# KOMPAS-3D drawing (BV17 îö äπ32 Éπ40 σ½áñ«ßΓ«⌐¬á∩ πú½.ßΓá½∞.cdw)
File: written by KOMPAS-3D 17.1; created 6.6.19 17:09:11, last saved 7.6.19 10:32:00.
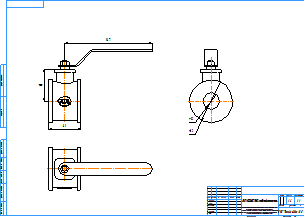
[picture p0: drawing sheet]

Sheet 1: A2, landscape

Title block, sheet 1: name: BV17 МФ Ду32 Ру40 хладостойкая угл.сталь; material: Сталь 20  ГОСТ 1050-2013; mass: 1,6; sheets: 1; sheet format: A2; stored path: C:\Users\kka\KOMPAS_Work\!Trash\BV17 МФ хладостойкая угл.сталь Ру40\KOMPAS 2D\BV17 МФ Ду20 Ру40 хладостойкая угл.сталь.cdw

Views: Вид 1, Проекционный вид 2, Проекционный вид 3
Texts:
  kka
  adl
  Рама для чертежей
  Лит-Масса-Масштаб
  Материал-Предприятие
  Масштаб
  Изм.
  Лист
  № докум.
  Подп.
  Дата
  Лит.
  Разраб.
  Пров.
  Т.контр.
  Листов
  Внимание! Данный продукт является объектом авторского права ООО «Торговый Дом АДЛ».
  Запрещается изменение, копирование, распространение
  (в том числе путем копирования на другие сайты и ресурсы в Интернете)
  или любое иное использование информации и объектов без предварительного
  согласия правообладателя (ООО «Торговый Дом АДЛ»).
  Н.контр.
  Утв.
  ООО "Торговый дом АДЛ"
  Изменение
  Номер документа
  Подпись
  Обозначение документа
  Наименование изделия
  Масса изделия по ГОСТ 2.109-73
  Порядковый номер листа
  Общее количество листов в документе
  Характер работы, выполненной лицом, подписавшим документ
  Наименование или индекс предприятия, выпускающего документ
  Инв. № подл.
  Подп. и дата
  Взам. инв. №
  Инв. № дубл.
  Инвентарный номер подлинника по ГОСТ 2.501-68
  Подпись принявшего подлинник в отдел технической документации
  Инвентарный номер подлинника, взамен которого выпущен данный подлинник
  Инвентарный номер дубликата по ГОСТ 2.502-68
  Подпись принявшего дубликат в отдел технической документации
  Справ. №
  Перв. примен.
  Обозначение документа, взамен или на основании которого выпущен данный документ
  Обозначение документа, в котором впервые записан данный документ
  Подпись лица, копировавшего чертеж
  Обозначение формата листа
  !Рама для чертежа
Dimensions and other numbers on the sheet: 61; 167; 32; 82; 1:1; 1; 1,6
